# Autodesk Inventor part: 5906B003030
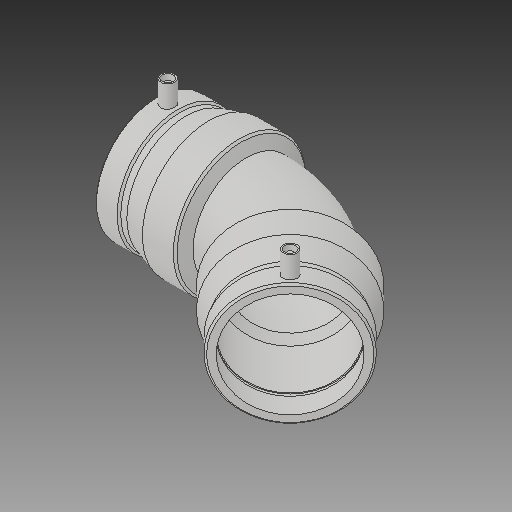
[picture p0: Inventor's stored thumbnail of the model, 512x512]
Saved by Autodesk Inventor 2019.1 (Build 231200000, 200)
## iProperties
Created: 2017-06
Part Number: 5906B003030
Material: Generic
Description: PLASSON 45° ELBOW 3''
Document SubType Name: Modeling
Designer: KIM
Mass: 55.0731 g
Surface Area: 148.067 cm^2
Volume: 55.0731 cm^3
Density: 1 g/cm^3
Appearance: Default
Author: KIM
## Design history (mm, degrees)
derived "5906B.ipt"
feature "Solid1::5906B.ipt"
tag "TaggingFeature1"
body "Solid1"
other parameters: "d_" = 88.7, "L_" = 230.124, "L_1" = 71.12, "D_" = 112.268, "A_" = 70.104, "d_2" = 12, "d2" = 112.268, "d4" = 57.531, "d5" = 101.0412, "d8" = 168 deg, "d10" = 28.448, "d11" = 9.48267, "d14" = 17.6296, "d18" = 88.7, "d19" = 3.52592, "d20" = 168 deg, "d22" = 103.28656, "d23" = 112.268, "d24" = 100.18796, "d29" = 70.104, "d30" = 15, "d31" = 80.5434, "d34" = 5 deg, "d35" = 12, "d39" = 0, "d41" = 4, "d42" = 14, "d43" = 0, "d44" = 9.6, "d45" = 4.8, "d46" = 6, "d47" = 0, "d49" = 88.7, "d50" = 75.395, "d51" = 28.448, "d52" = 71.12, "d54" = 135 deg, "d65" = 88.7, "d67" = 45 deg, "d71" = 135 deg, "d75" = 5.6134, "d82" = 45 deg, "d83" = 71.12, "d84" = 101.0412, "d86" = 50.5206, "d87" = 135 deg, "d88" = 230.124, "d90" = 71.12, "d91" = 0, "d92" = 71.12, "d93" = 0, "d94" = 135 deg, "d95" = 50.09398, "d98" = 230.124, "d99" = 69.0372, "d101" = 3, "d102" = 0, "d103" = 3, "d104" = 0, "d105" = 20.6248, "d106" = 5.1562
